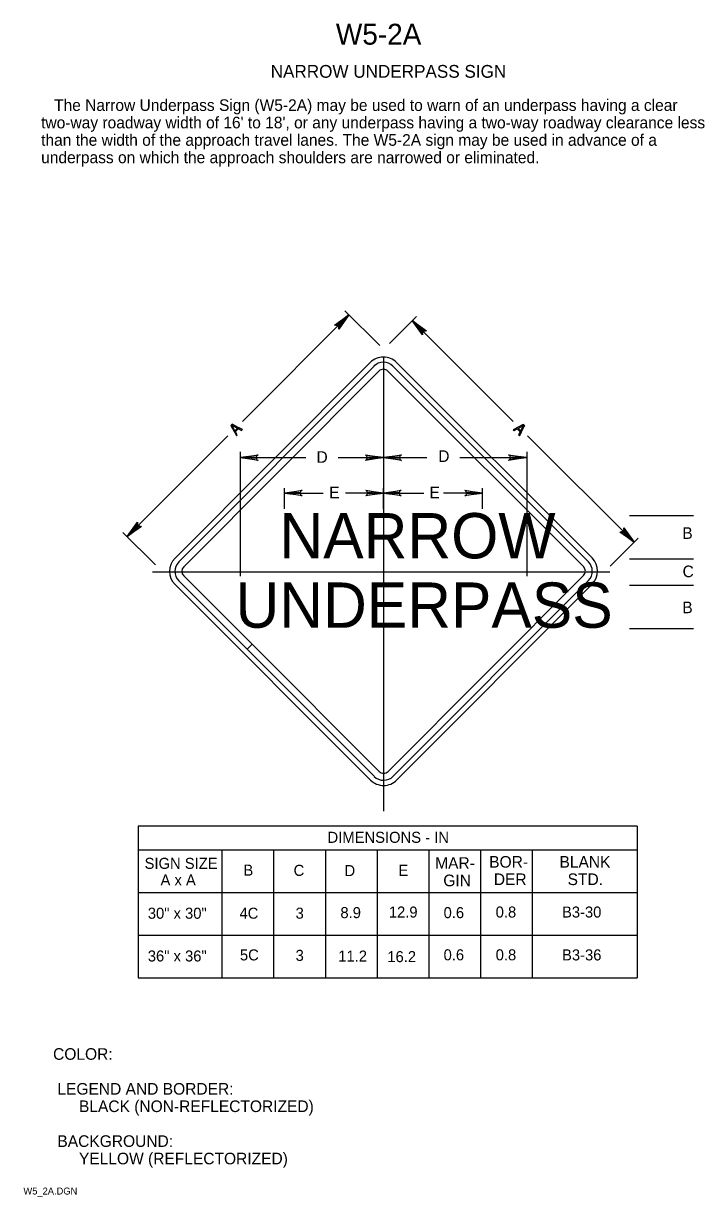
# Model space of a CAD drawing. Extents: x 0.03 to 0.176, y 0.006 to 0.258.
import ezdxf

# ---------------------------------------------------------------- set-up
doc = ezdxf.new("R2010")
doc.units = 0
for name, color, linetype in [('1', 7, 'Continuous'), ('2', 7, 'Continuous'), ('3', 7, 'Continuous')]:
    doc.layers.add(name, color=color, linetype=linetype)

# ---------------------------------------------------------------- blocks, each defined once
blk = doc.blocks.new('RARROW')
at = {"layer": '3'}
for p, q in [((-2.156, 0.285), (-2.2665, 0.384625)), ((-2.2665, 0.384625), (0, 0)), ((0, 0), (-2.2665, -0.379125)), ((-2.156, 0.285), (-2.075625, 0.12075)), ((0, 0), (-2.156, 0.285)), ((-2.14975, -0.2705), (0, 0)), ((-2.075625, 0.12075), (0, 0)), ((0, 0), (-2.074, -0.108)), ((-2.2665, -0.379125), (-2.14975, -0.2705)), ((-2.074, -0.108), (-2.14975, -0.2705))]:
    blk.add_line(p, q, dxfattribs=at)

msp = doc.modelspace()

# ---------------------------------------------------------------- linework, layer by layer
at = {"layer": '1'}
for p, q in [((0.10499, 0.1847), (0.06298, 0.14257)), ((0.15113, 0.14263), (0.10905, 0.18471)), ((0.06404, 0.14151), (0.10605, 0.18364)), ((0.10799, 0.18364), (0.15007, 0.14157)), ((0.07874, 0.12486), (0.06404, 0.13956)), ((0.15007, 0.13963), (0.10806, 0.09749)), ((0.06298, 0.1385), (0.07768, 0.1238)), ((0.10912, 0.09643), (0.15113, 0.13857)), ((0.07768, 0.1238), (0.07874, 0.12486)), ((0.07874, 0.12486), (0.07768, 0.1238)), ((0.07768, 0.1238), (0.10505, 0.09643)), ((0.10611, 0.09749), (0.07874, 0.12486))]:
    msp.add_line(p, q, dxfattribs=at)
for points in [[(0.07988, 0.16457), (0.07975, 0.16484), (0.07619, 0.16504), (0.07988, 0.16457), (0.08007, 0.16441), (0.07619, 0.16504), (0.07974, 0.16521), (0.07987, 0.16548), (0.07619, 0.16504), (0.08007, 0.16565), (0.07987, 0.16548)], [(0.10333, 0.1655), (0.10346, 0.16523), (0.10702, 0.16504), (0.10333, 0.1655), (0.10314, 0.16566), (0.10702, 0.16504), (0.10347, 0.16486), (0.10334, 0.1646), (0.10702, 0.16504), (0.10314, 0.16442), (0.10334, 0.1646)], [(0.11071, 0.16457), (0.11057, 0.16484), (0.10702, 0.16504), (0.11071, 0.16457), (0.1109, 0.16441), (0.10702, 0.16504), (0.11057, 0.16521), (0.1107, 0.16548), (0.10702, 0.16504), (0.1109, 0.16565), (0.1107, 0.16548)], [(0.13415, 0.1655), (0.13429, 0.16523), (0.13784, 0.16504), (0.13415, 0.1655), (0.13396, 0.16566), (0.13784, 0.16504), (0.13429, 0.16486), (0.13416, 0.1646), (0.13784, 0.16504), (0.13396, 0.16442), (0.13416, 0.1646)]]:
    msp.add_lwpolyline(points, dxfattribs=at)
for centre, radius, start, end in [((0.10702, 0.18267), 0.004, 45, 135.0864), ((0.10702, 0.18267), 0.00288, 45, 135.0864), ((0.10702, 0.18267), 0.00138, 45, 135.0864), ((0.06501, 0.14054), 0.004, 135.0864, 225), ((0.06501, 0.14054), 0.00288, 135.0864, 225), ((0.06501, 0.14054), 0.00137, 135.0864, 225), ((0.14909, 0.1406), 0.00137, 315.0864, 45), ((0.14909, 0.1406), 0.00287, 315.0864, 45), ((0.14909, 0.1406), 0.004, 315.0864, 45), ((0.10708, 0.09846), 0.00288, 225, 315.0864), ((0.10708, 0.09846), 0.00138, 225, 315.0864), ((0.10708, 0.09846), 0.004, 225, 315.0864)]:
    msp.add_arc(centre, radius, start, end, dxfattribs=at)
at = {"layer": '2'}
msp.add_line((0.16164, 0.08366), (0.16164, 0.06529), dxfattribs=at)
msp.add_line((0.16164, 0.08366), (0.16164, 0.06529), dxfattribs=at)
at = {"layer": '3'}
for p, q in [((0.07668, 0.17283), (0.0996, 0.19575)), ((0.10621, 0.18914), (0.09871, 0.19664)), ((0.10831, 0.18962), (0.1141, 0.19541)), ((0.13491, 0.17283), (0.11322, 0.19452)), ((0.06218, 0.14336), (0.10419, 0.1855)), ((0.10702, 0.18666), (0.10702, 0.08894)), ((0.15192, 0.14343), (0.10985, 0.1855)), ((0.07449, 0.17222), (0.07421, 0.17194)), ((0.07421, 0.17194), (0.07429, 0.17178)), ((0.07429, 0.17178), (0.0749, 0.17064)), ((0.07446, 0.17194), (0.07465, 0.17214)), ((0.07508, 0.17082), (0.07446, 0.17194)), ((0.07465, 0.17214), (0.07448, 0.17197)), ((0.07448, 0.17197), (0.0756, 0.17134)), ((0.07465, 0.17214), (0.07449, 0.17222)), ((0.07579, 0.17153), (0.07465, 0.17214)), ((0.13697, 0.1721), (0.13583, 0.17149)), ((0.13601, 0.17131), (0.13714, 0.17193)), ((0.13716, 0.17191), (0.13654, 0.17079)), ((0.13673, 0.1706), (0.13733, 0.17174)), ((0.13714, 0.17218), (0.13697, 0.1721)), ((0.13742, 0.1719), (0.13714, 0.17218)), ((0.13714, 0.17193), (0.13733, 0.17174)), ((0.13733, 0.17174), (0.13716, 0.17191)), ((0.13733, 0.17174), (0.13742, 0.1719)), ((0.07356, 0.16971), (0.05187, 0.14802)), ((0.0749, 0.17064), (0.07501, 0.17043)), ((0.07501, 0.17043), (0.07537, 0.16975)), ((0.07579, 0.17153), (0.07508, 0.17082)), ((0.07519, 0.17062), (0.076, 0.17143)), ((0.07556, 0.16995), (0.07519, 0.17062)), ((0.07537, 0.16975), (0.07556, 0.16995)), ((0.0756, 0.17134), (0.07579, 0.17153)), ((0.076, 0.17143), (0.07579, 0.17153)), ((0.076, 0.17143), (0.07581, 0.17124)), ((0.07581, 0.17124), (0.07648, 0.17087)), ((0.07668, 0.17107), (0.076, 0.17143)), ((0.07648, 0.17087), (0.07668, 0.17107)), ((0.13563, 0.17139), (0.13495, 0.17103)), ((0.13495, 0.17103), (0.13514, 0.17083)), ((0.13514, 0.17083), (0.13581, 0.1712)), ((0.13583, 0.17149), (0.13563, 0.17139)), ((0.13581, 0.1712), (0.13662, 0.17039)), ((0.13673, 0.1706), (0.13601, 0.17131)), ((0.13644, 0.17058), (0.13607, 0.16991)), ((0.13607, 0.16991), (0.13626, 0.16971)), ((0.13626, 0.16971), (0.13662, 0.17039)), ((0.13662, 0.17039), (0.13644, 0.17058)), ((0.13654, 0.17079), (0.13673, 0.1706)), ((0.13662, 0.17039), (0.13673, 0.1706)), ((0.13803, 0.16971), (0.16095, 0.1468)), ((0.10702, 0.16708), (0.10702, 0.16258)), ((0.07619, 0.16626), (0.07619, 0.13953)), ((0.07619, 0.16504), (0.09033, 0.16504)), ((0.09727, 0.16504), (0.10702, 0.16504)), ((0.10702, 0.16504), (0.11637, 0.16504)), ((0.12348, 0.16504), (0.13784, 0.16504)), ((0.13784, 0.16626), (0.13784, 0.13953)), ((0.08572, 0.15398), (0.08572, 0.15848)), ((0.08577, 0.1574), (0.09402, 0.1574)), ((0.10696, 0.1574), (0.09888, 0.1574)), ((0.10702, 0.15398), (0.10702, 0.15848)), ((0.10707, 0.1574), (0.11571, 0.1574)), ((0.12827, 0.1574), (0.11997, 0.1574)), ((0.12832, 0.15398), (0.12832, 0.15848)), ((0.15998, 0.1526), (0.17373, 0.1526)), ((0.05797, 0.14192), (0.05098, 0.14891)), ((0.15579, 0.14163), (0.16183, 0.14768)), ((0.15998, 0.14322), (0.17373, 0.14322)), ((0.05736, 0.14041), (0.15576, 0.14041)), ((0.10426, 0.09563), (0.06218, 0.13771)), ((0.10992, 0.09564), (0.15193, 0.13778)), ((0.15998, 0.1376), (0.17373, 0.1376)), ((0.15998, 0.12822), (0.17373, 0.12822)), ((0.05427, 0.0857), (0.05427, 0.05304)), ((0.16164, 0.0857), (0.05427, 0.0857)), ((0.05427, 0.0806), (0.16164, 0.0806)), ((0.07227, 0.0806), (0.07227, 0.05304)), ((0.05427, 0.07141), (0.16164, 0.07141)), ((0.05427, 0.06222), (0.16164, 0.06222)), ((0.05427, 0.05304), (0.16164, 0.05304))]:
    msp.add_line(p, q, dxfattribs=at)
for points in [[(0.16164, 0.0857), (0.16164, 0.05304)], [(0.16164, 0.08366), (0.16164, 0.06529)], [(0.08339, 0.0806), (0.08339, 0.05304)], [(0.09452, 0.0806), (0.09452, 0.05304)], [(0.10564, 0.0806), (0.10564, 0.05304)], [(0.11677, 0.0806), (0.11677, 0.05304)], [(0.11677, 0.0806), (0.11677, 0.05304)], [(0.12789, 0.0806), (0.12789, 0.05304)], [(0.13902, 0.0806), (0.13902, 0.05304)]]:
    msp.add_lwpolyline(points, dxfattribs=at)

# ---------------------------------------------------------------- block references
for p, xscale, yscale, rotation in [((0.0996, 0.19575), 0.0016545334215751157, 0.001636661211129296, 45), ((0.11322, 0.19452), 0.0016545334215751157, 0.001636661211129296, 135), ((0.08577, 0.1574), 0.0016545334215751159, 0.0016366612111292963, 180), ((0.10707, 0.1574), 0.0016545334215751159, 0.0016366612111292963, 180), ((0.05187, 0.14802), 0.001654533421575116, 0.001636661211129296, -135), ((0.16095, 0.1468), 0.001654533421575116, 0.001636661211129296, -45)]:
    msp.add_blockref('RARROW', p, dxfattribs=dict(at, xscale=xscale, yscale=yscale, rotation=rotation))
at = {"layer": '3', "xscale": 0.0016545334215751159, "yscale": 0.0016366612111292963}
for p in [(0.10696, 0.1574), (0.12827, 0.1574)]:
    msp.add_blockref('RARROW', p, dxfattribs=at)

# ---------------------------------------------------------------- texts
at = {"layer": '1'}
for s, height, p in [('W5-2A', 0.0045, (0.09679, 0.25391)), ('NARROW UNDERPASS SIGN', 0.0027503, (0.08276, 0.24679)), ('COLOR:', 0.0025, (0.03594, 0.03541)), (' LEGEND AND BORDER:', 0.0024998, (0.03594, 0.02791)), ('      BLACK (NON-REFLECTORIZED)', 0.0024998, (0.03594, 0.02416)), (' BACKGROUND:', 0.0024998, (0.03594, 0.01666)), ('      YELLOW (REFLECTORIZED)', 0.0024998, (0.03594, 0.01291)), ('W5_2A.DGN', 0.0015, (0.02956, 0.00641))]:
    msp.add_text(s, height=height, dxfattribs=at).set_placement(p)
at = {"layer": '2'}
for s, p in [('   The Narrow Underpass Sign (W5-2A) may be used to warn of an underpass having a clear', (0.03337, 0.23965)), ("two-way roadway width of 16' to 18', or any underpass having a two-way roadway clearance less ", (0.03337, 0.2359)), ('than the width of the approach travel lanes. The W5-2A sign may be used in advance of a ', (0.03337, 0.23215)), ('underpass on which the approach shoulders are narrowed or eliminated.', (0.03337, 0.2284))]:
    msp.add_text(s, height=0.0024998, dxfattribs=at).set_placement(p)
at = {"layer": '3'}
for s, height, p in [('D', 0.0025, (0.09261, 0.16391)), ('D', 0.0025, (0.11881, 0.16409)), ('E', 0.0025, (0.09535, 0.15628)), ('NARROW', 0.009751, (0.08465, 0.14334))]:
    msp.add_text(s, height=height, rotation=360, dxfattribs=at).set_placement(p)
for s, height, p in [('E', 0.0025, (0.11692, 0.15628)), ('B', 0.0025, (0.17133, 0.14754)), ('C', 0.0025, (0.17138, 0.13929)), ('UNDERPASS', 0.009751, (0.07519, 0.1284)), ('B', 0.0025, (0.17133, 0.13154)), ('DIMENSIONS - IN', 0.0023752, (0.095, 0.08211)), ('SIGN SIZE', 0.002375, (0.05563, 0.07651)), ('MAR-', 0.0025, (0.11815, 0.07652)), ('BOR-', 0.0025, (0.12977, 0.07677)), ('BLANK', 0.0025, (0.1449, 0.07677)), ('B', 0.00238, (0.07689, 0.07504)), ('C', 0.00238, (0.08769, 0.075)), ('D', 0.00238, (0.09864, 0.07495)), ('E', 0.00238, (0.11027, 0.075)), ('A x A', 0.002375, (0.05906, 0.07294)), ('GIN', 0.0025, (0.1199, 0.07277)), ('DER', 0.0025, (0.13077, 0.07302)), ('STD.', 0.0025, (0.14665, 0.07302)), ('30" x 30"', 0.002375, (0.05632, 0.06577)), ('4C', 0.002375, (0.07605, 0.06578)), ('3', 0.00238, (0.08812, 0.06578)), ('8.9', 0.002375, (0.09776, 0.0659)), ('12.9', 0.002375, (0.10818, 0.06603)), ('0.6', 0.002375, (0.11996, 0.0659)), ('0.8', 0.002375, (0.13117, 0.06603)), ('B3-30', 0.002375, (0.14544, 0.06603)), ('36" x 36"', 0.002375, (0.05632, 0.05657)), ('5C', 0.002375, (0.07614, 0.0568)), ('3', 0.00238, (0.08812, 0.0567)), ('11.2', 0.002375, (0.0973, 0.05655)), ('16.2', 0.002375, (0.10786, 0.05643)), ('0.6', 0.002375, (0.11996, 0.05682)), ('0.8', 0.002375, (0.13117, 0.05682)), ('B3-36', 0.002375, (0.14545, 0.0568))]:
    msp.add_text(s, height=height, dxfattribs=at).set_placement(p)

doc.saveas('drawing.dxf')
